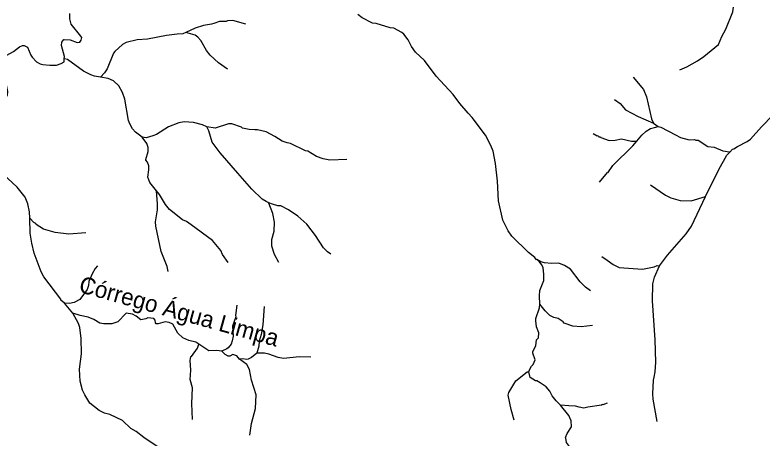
# Model space of a CAD drawing. Extents: x 393 to 446.6, y 8175.5 to 8231.
# Drawn here: x 397.02 to 404.19, y 8185.59 to 8189.65 of the extents above; entities that cross this region are included whole.
import ezdxf
from ezdxf.enums import TextEntityAlignment as Align

# ---------------------------------------------------------------- set-up
doc = ezdxf.new("R2010")
doc.units = 0
doc.header["$LTSCALE"] = 0.064
doc.linetypes.add('LONG_DASHED', pattern=[7.5, 6, -1.5])
doc.layers.add('61', color=7, linetype='Continuous')
doc.layers.add('7', color=7, linetype='Continuous', lineweight=25)
doc.layers.add('9', color=7, linetype='LONG_DASHED', lineweight=25)

msp = doc.modelspace()

# ---------------------------------------------------------------- linework, layer by layer
at = {"layer": '7'}
msp.add_line((397.57, 8186.7882), (397.4908, 8186.8836), dxfattribs=at)
for points in [[(397.4896, 8189.229), (397.4915, 8189.2517), (397.4612, 8189.3551), (397.4645, 8189.3889), (397.4851, 8189.4126), (397.4855, 8189.4131), (397.4883, 8189.413), (397.5452, 8189.4099), (397.613, 8189.3857), (397.6389, 8189.3873), (397.6518, 8189.4067), (397.6566, 8189.4326), (397.6485, 8189.447), (397.5565, 8189.5617), (397.5436, 8189.6134), (397.5436, 8189.6651)], [(399.2328, 8189.5603), (399.1083, 8189.5972), (399.0567, 8189.594), (399.0438, 8189.5876), (398.9792, 8189.5859), (398.9247, 8189.5678), (398.9017, 8189.5601), (398.8241, 8189.5472), (398.7466, 8189.5213), (398.6546, 8189.4805)], [(398.6546, 8189.4805), (398.6268, 8189.4682), (398.5722, 8189.4664), (398.4689, 8189.4519), (398.288, 8189.4164), (398.1879, 8189.4115), (398.0846, 8189.3857), (398.0474, 8189.3663), (397.9731, 8189.2985), (397.9618, 8189.2823), (397.9004, 8189.1322), (397.8762, 8189.0935), (397.836, 8189.0526), (397.8356, 8189.0521)], [(399.0559, 8189.1282), (398.9678, 8189.1903), (398.8903, 8189.2646), (398.8548, 8189.3098), (398.7999, 8189.4035), (398.7708, 8189.4374), (398.7466, 8189.4551), (398.6571, 8189.4798), (398.6546, 8189.4805)], [(396.9215, 8188.8568), (396.9324, 8188.8611), (396.944, 8188.8797), (396.9477, 8188.9142), (396.9283, 8189.0095), (396.9138, 8189.129), (396.9122, 8189.1968), (396.9251, 8189.242), (396.938, 8189.263), (397.0027, 8189.2985), (397.0608, 8189.3437), (397.0866, 8189.355), (397.1028, 8189.355), (397.1367, 8189.3405), (397.1673, 8189.2646), (397.1819, 8189.2436), (397.2222, 8189.1984), (397.2562, 8189.1806), (397.2836, 8189.1726), (397.3514, 8189.1677), (397.416, 8189.1693), (397.4596, 8189.1822), (397.4871, 8189.1984), (397.4896, 8189.229)], [(397.8356, 8189.0521), (397.7778, 8189.0627), (397.7455, 8189.0756), (397.6744, 8189.1112), (397.5194, 8189.221), (397.4915, 8189.2285), (397.4896, 8189.229)], [(398.2379, 8188.4781), (398.1734, 8188.5234), (398.1443, 8188.5573), (398.1168, 8188.6058), (398.1055, 8188.6381), (398.07, 8188.8415), (398.0474, 8188.9061), (398.0135, 8188.9707), (397.9618, 8189.0159), (397.9102, 8189.0385), (397.8356, 8189.0521)], [(397.1579, 8187.6994), (397.156, 8187.7596), (397.1399, 8187.8371), (397.114, 8187.9017), (397.0365, 8187.9954), (396.8589, 8188.1585), (396.8137, 8188.2085), (396.7782, 8188.257), (396.7507, 8188.328), (396.7394, 8188.3862), (396.7507, 8188.4669), (396.8589, 8188.6671), (396.888, 8188.7414), (396.9207, 8188.8541), (396.9215, 8188.8568)], [(398.8564, 8188.5747), (398.8145, 8188.5944), (398.7305, 8188.6187), (398.6401, 8188.6251), (398.5884, 8188.6138), (398.4883, 8188.5767), (398.3736, 8188.5024), (398.3397, 8188.4879), (398.2751, 8188.4717), (398.2379, 8188.4781)], [(400.2013, 8188.2612), (400.0385, 8188.2553), (399.9739, 8188.2699), (399.9093, 8188.2925), (399.8269, 8188.3425), (399.8027, 8188.3458), (399.6606, 8188.4168), (399.6283, 8188.4217), (399.5799, 8188.4394), (399.5104, 8188.4846), (399.4264, 8188.5266), (399.3441, 8188.5476), (399.3193, 8188.5481), (399.2634, 8188.5492), (399.1988, 8188.5621), (399.1891, 8188.5719), (399.0987, 8188.6058), (399.0663, 8188.6058), (398.9372, 8188.5638), (398.8564, 8188.5747)], [(399.4512, 8187.8477), (399.4268, 8187.8585), (399.3893, 8187.8823), (399.2875, 8187.9776), (399.154, 8188.1303), (398.984, 8188.3248), (398.9097, 8188.4298), (398.8774, 8188.538), (398.8564, 8188.5747)], [(398.3728, 8187.9625), (398.309, 8188.0406), (398.2912, 8188.0923), (398.3009, 8188.1633), (398.2993, 8188.2021), (398.288, 8188.2376), (398.2719, 8188.2554), (398.2706, 8188.2638), (398.2928, 8188.3377), (398.2928, 8188.3765), (398.2799, 8188.4152), (398.2379, 8188.4781)], [(398.4859, 8187.1884), (398.4766, 8187.2361), (398.4204, 8187.3785), (398.3687, 8187.624), (398.3639, 8187.6627), (398.3849, 8187.779), (398.3849, 8187.8371), (398.3728, 8187.9625)], [(399.0612, 8187.2733), (399.0066, 8187.3495), (398.9904, 8187.3882), (398.9129, 8187.4851), (398.7079, 8187.6353), (398.6626, 8187.6659), (398.6239, 8187.6837), (398.4996, 8187.7822), (398.4608, 8187.8291), (398.4027, 8187.9259), (398.3728, 8187.9625)], [(399.5492, 8187.2747), (399.5056, 8187.3495), (399.4797, 8187.4302), (399.4797, 8187.4948), (399.5039, 8187.5755), (399.5072, 8187.6595), (399.4894, 8187.7435), (399.4524, 8187.8445), (399.4512, 8187.8477)], [(400.0483, 8187.3529), (400.0157, 8187.3762), (399.9771, 8187.4156), (399.9012, 8187.5336), (399.8172, 8187.6401), (399.73, 8187.7192), (399.6412, 8187.7806), (399.5669, 8187.8177), (399.5395, 8187.8177), (399.4862, 8187.8323), (399.4512, 8187.8477)], [(397.4908, 8186.8836), (397.457, 8186.9115), (397.4548, 8186.9215), (397.2917, 8187.1363), (397.2658, 8187.1848), (397.2012, 8187.3624), (397.177, 8187.4593), (397.1625, 8187.5562), (397.1579, 8187.6994)], [(397.6955, 8187.5573), (397.5323, 8187.5449), (397.4031, 8187.5626), (397.2899, 8187.5946), (397.2177, 8187.6388), (397.2174, 8187.6466), (397.1964, 8187.6579), (397.1592, 8187.698), (397.1579, 8187.6994)], [(397.8082, 8187.2406), (397.7858, 8187.2154), (397.7567, 8187.1654), (397.7261, 8187.0911), (397.7212, 8187.0524), (397.7083, 8187.0136), (397.6372, 8186.9183), (397.5839, 8186.8908), (397.5404, 8186.8795), (397.4908, 8186.8836)], [(399.1445, 8186.8644), (399.1309, 8186.7649), (399.1342, 8186.752), (399.1051, 8186.6616), (399.1086, 8186.5671), (399.1017, 8186.5217), (399.0912, 8186.4903), (399.0609, 8186.4554), (399.0486, 8186.4436), (398.9998, 8186.4217)], [(398.7803, 8186.489), (398.7517, 8186.508), (398.6853, 8186.5259), (398.6271, 8186.5517), (398.5787, 8186.597), (398.5302, 8186.681), (398.4947, 8186.6987), (398.456, 8186.7035), (398.3914, 8186.6858), (398.372, 8186.6858), (398.3639, 8186.6939), (398.3607, 8186.7197), (398.3477, 8186.7358), (398.2913, 8186.7439), (398.2719, 8186.7342), (398.225, 8186.7245), (398.1782, 8186.76), (398.1427, 8186.7778), (398.0846, 8186.7859), (398.0038, 8186.7051), (397.9457, 8186.6858), (397.8682, 8186.6842), (397.8294, 8186.6922), (397.7713, 8186.7277), (397.7196, 8186.7503), (397.6421, 8186.7649), (397.57, 8186.7882)], [(398.4105, 8185.4892), (398.2541, 8185.5926), (398.1782, 8185.6523), (398.1265, 8185.6813), (398.0474, 8185.7573), (397.9263, 8185.8154), (397.8746, 8185.8283), (397.8246, 8185.8525), (397.7341, 8185.9252), (397.6857, 8186.0027), (397.6647, 8186.048), (397.6421, 8186.1352), (397.6356, 8186.2514), (397.6534, 8186.3967), (397.6518, 8186.5453), (397.6372, 8186.6487), (397.6243, 8186.6874), (397.57, 8186.7882)], [(399.4079, 8186.853), (399.3957, 8186.6745), (399.378, 8186.5841), (399.3586, 8186.5195), (399.357, 8186.4694), (399.3383, 8186.4034)], [(398.7206, 8185.7653), (398.7143, 8185.922), (398.7191, 8186.0706), (398.6965, 8186.1513), (398.703, 8186.2417), (398.6965, 8186.3322), (398.703, 8186.3709), (398.7095, 8186.3725), (398.7692, 8186.4517), (398.7803, 8186.489)], [(398.9998, 8186.4217), (398.9501, 8186.4306), (398.8758, 8186.4258), (398.7803, 8186.489)], [(399.1711, 8186.3453), (399.1466, 8186.3779), (399.1083, 8186.3919), (399.0776, 8186.3741), (399.0631, 8186.3757), (399.0324, 8186.3919), (398.9998, 8186.4217)], [(399.3383, 8186.4034), (399.2843, 8186.3612), (399.2537, 8186.3466), (399.2375, 8186.3434), (399.202, 8186.3499), (399.1711, 8186.3453)], [(399.8563, 8186.3653), (399.7478, 8186.3677), (399.5928, 8186.3531), (399.5411, 8186.3612), (399.4507, 8186.3951), (399.4119, 8186.4032), (399.3383, 8186.4034)], [(399.27, 8185.618), (399.2859, 8185.7282), (399.3247, 8185.8736), (399.3312, 8186.0027), (399.2843, 8186.1448), (399.2682, 8186.2482), (399.2423, 8186.295), (399.1711, 8186.3453)]]:
    msp.add_lwpolyline(points, dxfattribs=at)
at = {"layer": '9'}
msp.add_line((403.1454, 8188.6104), (403.1893, 8188.5779), dxfattribs=at)
for points in [[(403.3957, 8189.1228), (403.4651, 8189.1516), (403.5652, 8189.2081), (403.6281, 8189.2517), (403.767, 8189.3663), (403.7993, 8189.4422), (403.838, 8189.5133), (403.9059, 8189.6796), (403.9285, 8189.8429), (403.9365, 8189.9009), (403.9462, 8190.1302), (403.9721, 8190.269), (403.9874, 8190.3026)], [(402.0247, 8187.3022), (402.0214, 8187.2994), (402.0053, 8187.322), (401.9439, 8187.3688), (401.7856, 8187.5271), (401.7501, 8187.5771), (401.6968, 8187.6789), (401.6548, 8187.8662), (401.6468, 8188.0551), (401.6274, 8188.2231), (401.6048, 8188.341), (401.5838, 8188.3975), (401.5305, 8188.496), (401.4029, 8188.6639), (401.3658, 8188.7071), (401.2851, 8188.8012), (401.2205, 8188.8867), (401.0574, 8189.0628), (400.946, 8189.2113), (400.8604, 8189.2921), (400.8216, 8189.347), (400.7909, 8189.4099), (400.7473, 8189.4649), (400.728, 8189.4826), (400.6521, 8189.5213), (400.6166, 8189.5262), (400.4809, 8189.5682), (400.447, 8189.5714), (400.3485, 8189.6214), (400.3049, 8189.6538)], [(402.949, 8189.0532), (403.0468, 8188.9352), (403.0775, 8188.8625), (403.1243, 8188.6542), (403.1454, 8188.6104)], [(402.7708, 8188.8397), (402.8224, 8188.7995), (402.8756, 8188.7398), (402.9968, 8188.6752), (403.1454, 8188.6104)], [(403.8768, 8188.3341), (403.9031, 8188.3615), (403.9155, 8188.3635), (403.9511, 8188.3878), (404.0432, 8188.4346), (404.0738, 8188.4588), (404.1804, 8188.5767), (404.2902, 8188.6881), (404.3055, 8188.6961)], [(402.9827, 8188.4384), (403.0323, 8188.4969), (403.0743, 8188.5354), (403.114, 8188.5598), (403.1519, 8188.5697), (403.1893, 8188.5779)], [(403.1893, 8188.5779), (403.215, 8188.5732), (403.3536, 8188.5004), (403.4021, 8188.475), (403.4877, 8188.4523), (403.5361, 8188.454), (403.5506, 8188.4475), (403.5732, 8188.4475), (403.6653, 8188.3877), (403.725, 8188.3797), (403.809, 8188.3442), (403.8728, 8188.3347), (403.8768, 8188.3341)], [(402.5641, 8188.5129), (402.6027, 8188.4908), (402.6124, 8188.4911), (402.6205, 8188.4814), (402.6351, 8188.4798), (402.6383, 8188.4733), (402.719, 8188.4443), (402.7772, 8188.4475), (402.8369, 8188.4605), (402.9322, 8188.4394), (402.9798, 8188.4385), (402.9827, 8188.4384)], [(402.6262, 8188.0462), (402.7009, 8188.136), (402.7061, 8188.1359), (402.7545, 8188.2037), (402.9451, 8188.3942), (402.9827, 8188.4384)], [(403.644, 8187.9057), (403.7702, 8188.1666), (403.8477, 8188.3038), (403.8768, 8188.3341)], [(403.116, 8188.0204), (403.2584, 8187.9195), (403.31, 8187.8936), (403.3988, 8187.8678), (403.5054, 8187.8662), (403.644, 8187.9057)], [(403.2, 8187.2433), (403.2777, 8187.343), (403.4586, 8187.5481), (403.507, 8187.6224), (403.644, 8187.9057)], [(402.0529, 8186.8736), (402.0482, 8186.9541), (402.0537, 8187.0055), (402.0908, 8187.1008), (402.0925, 8187.1605), (402.086, 8187.2235), (402.0731, 8187.2526), (402.0457, 8187.2847), (402.0247, 8187.3022)], [(402.5378, 8187.0033), (402.4911, 8187.0371), (402.4396, 8187.0895), (402.346, 8187.209), (402.2911, 8187.2461), (402.2346, 8187.2687), (402.1651, 8187.2655), (402.0989, 8187.2703), (402.0634, 8187.28), (402.0247, 8187.3022)], [(402.6472, 8187.3311), (402.6985, 8187.2954), (402.7578, 8187.2542), (402.8159, 8187.2251), (403.0371, 8187.2106), (403.1502, 8187.2316), (403.1776, 8187.2445), (403.2, 8187.2433)], [(403.1791, 8185.7483), (403.1421, 8185.9608), (403.1388, 8186.0124), (403.1453, 8186.1448), (403.1506, 8186.1736), (403.1598, 8186.2239), (403.1647, 8186.316), (403.1598, 8186.5324), (403.134, 8186.907), (403.1389, 8187.0701), (403.155, 8187.1331), (403.2, 8187.2433)], [(401.9487, 8186.2255), (401.9528, 8186.2447), (401.9715, 8186.2786), (401.9891, 8186.295), (402.0069, 8186.3402), (401.9859, 8186.4032), (401.9859, 8186.4194), (402.0133, 8186.4726), (402.0198, 8186.5324), (402.0408, 8186.5518), (402.044, 8186.5986), (402.0198, 8186.6551), (402.0133, 8186.7132), (402.015, 8186.7375), (402.0488, 8186.8392), (402.0529, 8186.8736)], [(402.5578, 8186.6685), (402.4493, 8186.6551), (402.3702, 8186.6631), (402.2879, 8186.6922), (402.2782, 8186.7052), (402.2297, 8186.7358), (402.1861, 8186.7471), (402.1474, 8186.7665), (402.1037, 8186.8085), (402.0529, 8186.8736)], [(401.8076, 8185.7611), (401.7776, 8185.8622), (401.7485, 8186.0011), (401.7566, 8186.0269), (401.8228, 8186.1368), (401.931, 8186.2255), (401.9487, 8186.2255)], [(402.2527, 8185.9049), (402.2108, 8185.9448), (402.1716, 8185.993), (402.149, 8186.0399), (402.1134, 8186.0802), (402.0569, 8186.119), (402.0246, 8186.1367), (402.0101, 8186.1367), (401.9617, 8186.169), (401.9487, 8186.2255)], [(402.7005, 8185.9249), (402.6584, 8185.9085), (402.6544, 8185.9123), (402.6447, 8185.9058), (402.5123, 8185.8864), (402.4766, 8185.877), (402.4291, 8185.8863), (402.3961, 8185.8962), (402.3314, 8185.8977), (402.2527, 8185.9049)], [(402.6082, 8184.6981), (402.551, 8184.8252), (402.5462, 8184.853), (402.5252, 8184.8998), (402.4703, 8184.9854), (402.4477, 8185.0322), (402.3331, 8185.1824), (402.2959, 8185.2518), (402.2846, 8185.3584), (402.333, 8185.4505), (402.3395, 8185.4941), (402.3377, 8185.5063), (402.3086, 8185.5472), (402.3014, 8185.5885), (402.3007, 8185.5926), (402.3137, 8185.6329), (402.3573, 8185.6959), (402.3541, 8185.7541), (402.3298, 8185.8041), (402.2527, 8185.9049)]]:
    msp.add_lwpolyline(points, dxfattribs=at)

# ---------------------------------------------------------------- texts
at = {"layer": '61'}
msp.add_text('Córrego Água Limpa', height=0.16, rotation=344.497, dxfattribs=at).set_placement((398.5705, 8186.7291), align=Align.CENTER)

doc.saveas('drawing.dxf')
